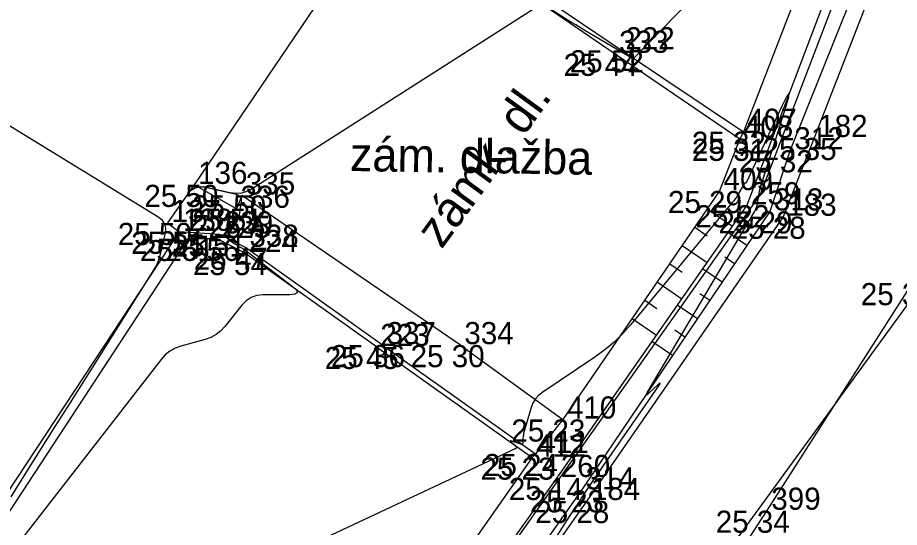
# Model space of a CAD drawing. Extents: x -702257 to -701487, y -1009871 to -1008841.
# Drawn here: x -701777.89 to -701767.92, y -1009411.95 to -1009406.19 of the extents above; entities that cross this region are included whole.
import ezdxf

# ---------------------------------------------------------------- set-up
doc = ezdxf.new("R2010")
doc.units = 0
for name, color, linetype in [('Ex_Minor Contours', 7, 'Continuous'), ('Z_body', 7, 'Continuous'), ('Z_body_cisla', 7, 'Continuous'), ('Z_body_vysky_redukovane', 7, 'Continuous'), ('Z_hrany_paty', 7, 'Continuous'), ('Z_katastr_hranice', 7, 'Continuous'), ('Z_komunikace', 7, 'Continuous'), ('Z_obruba', 7, 'Continuous'), ('Z_popisy', 7, 'Continuous'), ('Z_rozhranni', 7, 'Continuous'), ('Z_technicke_srafy', 7, 'Continuous'), ('Z_vstupy', 7, 'Continuous'), ('Z_zlabek', 7, 'Continuous')]:
    doc.layers.add(name, color=color, linetype=linetype)

# ---------------------------------------------------------------- blocks, each defined once
blk = doc.blocks.new('POINT_DISPLAY')
blk.add_line((0, 0), (0, 0))

msp = doc.modelspace()

# ---------------------------------------------------------------- linework, layer by layer
at = {"layer": 'Ex_Minor Contours'}
for points in [[(-701770.2687, -1009405.9803), (-701770.9201, -1009406.6501), (-701770.9233, -1009406.6523), (-701770.9311, -1009406.6547), (-701770.9335, -1009406.6544), (-701770.9347, -1009406.6539), (-701771.0594, -1009406.5807), (-701771.1137, -1009406.5486), (-701771.4793, -1009406.3332), (-701771.5277, -1009406.3044), (-701771.5759, -1009406.2752), (-701771.6239, -1009406.2456), (-701771.6716, -1009406.2156), (-701771.862, -1009406.0947)], [(-701772.0522, -1009406.0949), (-701775.2334, -1009408.1256), (-701775.2929, -1009408.1563), (-701775.3546, -1009408.1739), (-701775.4187, -1009408.1785), (-701775.485, -1009408.17), (-701775.762, -1009408.1084), (-701775.8227, -1009408.1027), (-701775.8768, -1009408.114), (-701775.9242, -1009408.1422), (-701775.965, -1009408.1875), (-701775.9242, -1009408.1422), (-701775.8768, -1009408.114), (-701775.8227, -1009408.1027), (-701775.762, -1009408.1084), (-701775.414, -1009408.1858), (-701775.3866, -1009408.1961), (-701775.3682, -1009408.2127), (-701775.3589, -1009408.2357), (-701775.3588, -1009408.265), (-701775.3763, -1009408.3956), (-701775.3823, -1009408.4272), (-701775.3917, -1009408.4575), (-701775.4045, -1009408.4866), (-701775.4206, -1009408.5144), (-701775.5088, -1009408.649), (-701775.5153, -1009408.6627), (-701775.5159, -1009408.6753), (-701775.5107, -1009408.6869), (-701775.4998, -1009408.6973), (-701775.4407, -1009408.7395), (-701775.4286, -1009408.7479), (-701775.4163, -1009408.7561), (-701775.4038, -1009408.7639), (-701775.3911, -1009408.7714), (-701775.3399, -1009408.801), (-701775.3272, -1009408.8085), (-701775.3148, -1009408.8165), (-701775.3027, -1009408.8249), (-701775.2909, -1009408.8337), (-701774.7769, -1009409.2294), (-701774.7342, -1009409.2696), (-701774.7252, -1009409.2984), (-701774.7498, -1009409.3159), (-701774.8082, -1009409.322), (-701775.1105, -1009409.3236), (-701775.1814, -1009409.3313), (-701775.2453, -1009409.3534), (-701775.3021, -1009409.3899), (-701775.352, -1009409.4409), (-701775.5418, -1009409.6793), (-701775.5889, -1009409.7301), (-701775.6421, -1009409.7717), (-701775.7012, -1009409.8042), (-701775.7664, -1009409.8275), (-701776.0393, -1009409.9026), (-701776.1045, -1009409.926), (-701776.1634, -1009409.9587), (-701776.2162, -1009410.0006), (-701776.2628, -1009410.0518), (-701779.331, -1009413.9893)], [(-701777.9599, -1009411.6023), (-701777.7932, -1009411.3379), (-701777.6265, -1009411.0735), (-701777.4596, -1009410.8091), (-701777.2926, -1009410.5449), (-701776.352, -1009409.0569), (-701776.3235, -1009409.0073), (-701776.2996, -1009408.9558), (-701776.2802, -1009408.9024), (-701776.2654, -1009408.8471), (-701776.2151, -1009408.6224), (-701776.2103, -1009408.5695), (-701776.2208, -1009408.5231), (-701776.2468, -1009408.4832), (-701776.2882, -1009408.4498), (-701779.1479, -1009406.6973)], [(-701772.0715, -1009412.4916), (-701771.6383, -1009411.8155), (-701771.5616, -1009411.6971), (-701771.4839, -1009411.5794), (-701771.4052, -1009411.4623), (-701771.3255, -1009411.3459), (-701770.637, -1009410.3505), (-701770.6231, -1009410.3287), (-701770.6204, -1009410.3197), (-701770.6288, -1009410.3237), (-701770.6485, -1009410.3405), (-701770.7495, -1009410.4335), (-701770.7694, -1009410.4502), (-701770.7786, -1009410.4536), (-701770.7771, -1009410.4439), (-701770.7649, -1009410.421), (-701769.5565, -1009408.387), (-701769.5437, -1009408.3631), (-701769.5333, -1009408.3383), (-701769.5253, -1009408.3126), (-701769.5197, -1009408.286), (-701769.5019, -1009408.178), (-701769.497, -1009408.1511), (-701769.4911, -1009408.1245), (-701769.4843, -1009408.098), (-701769.4765, -1009408.0718), (-701769.2023, -1009407.2017), (-701769.1685, -1009407.0855), (-701769.1638, -1009407.0442), (-701769.1884, -1009407.0778), (-701769.2421, -1009407.1862), (-701769.6504, -1009408.0577), (-701769.6525, -1009408.0601), (-701769.6557, -1009408.0608), (-701769.663, -1009408.0603), (-701769.6662, -1009408.0609), (-701769.6685, -1009408.0632), (-701769.7463, -1009408.1961), (-701769.76, -1009408.2184), (-701769.7746, -1009408.2402), (-701769.7901, -1009408.2613), (-701769.8065, -1009408.2818), (-701770.9523, -1009409.6567), (-701771.0444, -1009409.7597), (-701771.1432, -1009409.8554), (-701771.2485, -1009409.9439), (-701771.3604, -1009410.025), (-701771.9598, -1009410.4284), (-701772.0018, -1009410.462), (-701772.036, -1009410.5012), (-701772.0626, -1009410.5459), (-701772.0815, -1009410.5963), (-701772.1647, -1009410.8903), (-701772.1678, -1009410.9027), (-701772.1701, -1009410.9152), (-701772.1716, -1009410.9279), (-701772.1723, -1009410.9406), (-701772.1735, -1009410.9919), (-701772.1753, -1009411.0026), (-701772.1801, -1009411.009), (-701772.1878, -1009411.0113), (-701772.1984, -1009411.0093), (-701772.2994, -1009410.975), (-701772.3112, -1009410.9717), (-701772.3161, -1009410.9723), (-701772.314, -1009410.9768), (-701772.305, -1009410.9851), (-701772.255, -1009411.0259), (-701772.2459, -1009411.0357), (-701772.2436, -1009411.0447), (-701772.248, -1009411.0528), (-701772.2592, -1009411.0601), (-701774.4607, -1009412.0932)]]:
    msp.add_lwpolyline(points, dxfattribs=at)
at = {"layer": 'Z_hrany_paty'}
for p, q in [((-701767.68, -1009403.12), (-701769.64, -1009408.31)), ((-701769.64, -1009408.31), (-701771.79, -1009411.39)), ((-701771.79, -1009411.39), (-701776.37, -1009417.78))]:
    msp.add_line(p, q, dxfattribs=at)
at = {"layer": 'Z_katastr_hranice'}
for p, q in [((-701752.99, -1009364.98), (-701769.49, -1009408.19)), ((-701769.49, -1009408.19), (-701878.35, -1009561.73)), ((-701767.63, -1009409.16), (-701770.02, -1009412.44))]:
    msp.add_line(p, q, dxfattribs=at)
at = {"layer": 'Z_komunikace'}
for p, q in [((-701773.5, -1009404.56), (-701775.89, -1009408.08)), ((-701775.89, -1009408.08), (-701776.19, -1009408.51)), ((-701776.19, -1009408.51), (-701776.06, -1009408.61)), ((-701776.06, -1009408.61), (-701780.9, -1009415.95))]:
    msp.add_line(p, q, dxfattribs=at)
at = {"layer": 'Z_obruba'}
for p, q in [((-701767.23, -1009403.31), (-701768.88, -1009407.55)), ((-701772.99, -1009405.25), (-701771.06, -1009406.56)), ((-701771.06, -1009406.56), (-701769.68, -1009407.48)), ((-701768.88, -1009407.55), (-701769.23, -1009408.44)), ((-701769.23, -1009408.44), (-701771.45, -1009411.65)), ((-701775.96, -1009408.69), (-701780.76, -1009416)), ((-701775.63, -1009408.69), (-701775.96, -1009408.69)), ((-701775.32, -1009408.85), (-701775.63, -1009408.69)), ((-701773.83, -1009409.91), (-701775.32, -1009408.85)), ((-701773.83, -1009409.91), (-701772.07, -1009411.16)), ((-701771.45, -1009411.65), (-701776.06, -1009418.18))]:
    msp.add_line(p, q, dxfattribs=at)
at = {"layer": 'Z_rozhranni'}
for p, q in [((-701767.37, -1009403.25), (-701769.15, -1009407.69)), ((-701767.37, -1009403.25), (-701769.15, -1009407.69)), ((-701773.06, -1009405.28), (-701771.13, -1009406.6)), ((-701773.06, -1009405.28), (-701771.13, -1009406.6)), ((-701771.13, -1009406.6), (-701769.72, -1009407.56)), ((-701771.13, -1009406.6), (-701769.72, -1009407.56)), ((-701769.15, -1009407.69), (-701769.38, -1009408.38)), ((-701769.15, -1009407.69), (-701769.38, -1009408.38)), ((-701775.41, -1009408.35), (-701775.89, -1009408.08)), ((-701775.41, -1009408.35), (-701775.89, -1009408.08)), ((-701775.35, -1009408.2), (-701775.41, -1009408.35)), ((-701775.35, -1009408.2), (-701775.41, -1009408.35)), ((-701772.88, -1009409.89), (-701775.35, -1009408.2)), ((-701772.88, -1009409.89), (-701775.35, -1009408.2)), ((-701769.38, -1009408.38), (-701771.51, -1009411.53)), ((-701769.38, -1009408.38), (-701771.51, -1009411.53)), ((-701775.6, -1009408.64), (-701776.06, -1009408.61)), ((-701775.6, -1009408.64), (-701776.06, -1009408.61)), ((-701775.31, -1009408.79), (-701775.6, -1009408.64)), ((-701775.31, -1009408.79), (-701775.6, -1009408.64)), ((-701773.76, -1009409.89), (-701775.31, -1009408.79)), ((-701773.76, -1009409.89), (-701775.31, -1009408.79)), ((-701773.76, -1009409.89), (-701772.03, -1009411.12)), ((-701773.76, -1009409.89), (-701772.03, -1009411.12)), ((-701772.88, -1009409.89), (-701771.72, -1009410.73)), ((-701772.88, -1009409.89), (-701771.72, -1009410.73)), ((-701771.51, -1009411.53), (-701776.18, -1009418.09)), ((-701771.51, -1009411.53), (-701776.18, -1009418.09))]:
    msp.add_line(p, q, dxfattribs=at)
at = {"layer": 'Z_technicke_srafy'}
for p, q in [((-701770.089, -1009408.352), (-701769.805, -1009408.547)), ((-701770.23, -1009408.558), (-701770.089, -1009408.655)), ((-701769.641, -1009408.766), (-701769.856, -1009408.62)), ((-701770.372, -1009408.764), (-701770.091, -1009408.957)), ((-701770.513, -1009408.971), (-701770.374, -1009409.066)), ((-701769.781, -1009408.973), (-701769.89, -1009408.899)), ((-701769.921, -1009409.18), (-701770.143, -1009409.03)), ((-701770.654, -1009409.177), (-701770.378, -1009409.367)), ((-701770.061, -1009409.387), (-701770.173, -1009409.311)), ((-701770.796, -1009409.383), (-701770.658, -1009409.477)), ((-701770.201, -1009409.594), (-701770.429, -1009409.44)), ((-701770.937, -1009409.589), (-701770.664, -1009409.777)), ((-701770.341, -1009409.801), (-701770.457, -1009409.723)), ((-701770.481, -1009410.008), (-701770.715, -1009409.85))]:
    msp.add_line(p, q, dxfattribs=at)
at = {"layer": 'Z_vstupy'}
for p, q in [((-701769.41, -1009411.76), (-701767.77, -1009409.19)), ((-701769.41, -1009411.76), (-701767.77, -1009409.19)), ((-701770.09, -1009412.78), (-701769.41, -1009411.76)), ((-701770.09, -1009412.78), (-701769.41, -1009411.76))]:
    msp.add_line(p, q, dxfattribs=at)
at = {"layer": 'Z_zlabek'}
for p, q in [((-701767.94, -1009402.99), (-701769.68, -1009407.48)), ((-701767.94, -1009402.99), (-701769.68, -1009407.48)), ((-701769.68, -1009407.48), (-701769.72, -1009407.56)), ((-701769.68, -1009407.48), (-701769.72, -1009407.56)), ((-701769.72, -1009407.56), (-701769.95, -1009408.15)), ((-701769.72, -1009407.56), (-701769.95, -1009408.15)), ((-701769.95, -1009408.15), (-701771.72, -1009410.73)), ((-701769.95, -1009408.15), (-701771.72, -1009410.73)), ((-701771.72, -1009410.73), (-701772.03, -1009411.12)), ((-701771.72, -1009410.73), (-701772.03, -1009411.12)), ((-701772.07, -1009411.16), (-701776.57, -1009417.57)), ((-701772.07, -1009411.16), (-701776.57, -1009417.57)), ((-701772.03, -1009411.12), (-701772.07, -1009411.16)), ((-701772.03, -1009411.12), (-701772.07, -1009411.16))]:
    msp.add_line(p, q, dxfattribs=at)

# ---------------------------------------------------------------- block references
at = {"layer": 'Z_body'}
for p in [(-701771.06, -1009406.56), (-701771.13, -1009406.6), (-701769.68, -1009407.48), (-701769.72, -1009407.56), (-701768.88, -1009407.55), (-701769.15, -1009407.69), (-701775.89, -1009408.08), (-701769.95, -1009408.15), (-701775.35, -1009408.2), (-701775.41, -1009408.35), (-701769.64, -1009408.31), (-701769.38, -1009408.38), (-701769.23, -1009408.44), (-701776.19, -1009408.51), (-701776.06, -1009408.61), (-701775.6, -1009408.64), (-701775.96, -1009408.69), (-701775.63, -1009408.69), (-701775.32, -1009408.85), (-701775.31, -1009408.79), (-701773.83, -1009409.91), (-701773.76, -1009409.89), (-701772.88, -1009409.89), (-701771.72, -1009410.73), (-701772.07, -1009411.16), (-701772.03, -1009411.12), (-701771.79, -1009411.39), (-701771.51, -1009411.53), (-701771.45, -1009411.65), (-701769.41, -1009411.76)]:
    msp.add_blockref('POINT_DISPLAY', p, dxfattribs=at)

# ---------------------------------------------------------------- texts
at = {"layer": 'Z_body_cisla'}
for s, p in [('333', (-701771.085, -1009406.59)), ('222', (-701771.015, -1009406.55)), ('407', (-701769.635, -1009407.47)), ('408', (-701769.675, -1009407.55)), ('182', (-701768.835, -1009407.54)), ('312', (-701769.105, -1009407.68)), ('136', (-701775.845, -1009408.07)), ('335', (-701775.305, -1009408.19)), ('409', (-701769.905, -1009408.14)), ('259', (-701769.595, -1009408.3)), ('336', (-701775.365, -1009408.34)), ('313', (-701769.335, -1009408.37)), ('183', (-701769.185, -1009408.43)), ('137', (-701776.145, -1009408.5)), ('138', (-701776.015, -1009408.6)), ('339', (-701775.555, -1009408.63)), ('226', (-701775.915, -1009408.68)), ('225', (-701775.585, -1009408.68)), ('338', (-701775.265, -1009408.78)), ('224', (-701775.275, -1009408.84)), ('223', (-701773.785, -1009409.9)), ('337', (-701773.715, -1009409.88)), ('334', (-701772.835, -1009409.88)), ('410', (-701771.675, -1009410.72)), ('411', (-701771.985, -1009411.11)), ('412', (-701772.025, -1009411.15)), ('260', (-701771.745, -1009411.38)), ('314', (-701771.465, -1009411.52)), ('184', (-701771.405, -1009411.64)), ('399', (-701769.365, -1009411.75))]:
    msp.add_text(s, height=0.25, dxfattribs=at).set_placement(p)
at = {"layer": 'Z_body_vysky_redukovane'}
for s, p in [('25 52', (-701771.6433, -1009406.81)), ('25 44', (-701771.7133, -1009406.85)), ('25 32', (-701770.2633, -1009407.73)), ('25 31', (-701770.2617, -1009407.81)), ('25 35', (-701769.4633, -1009407.8)), ('25 32', (-701769.7333, -1009407.94)), ('25 50', (-701776.4525, -1009408.33)), ('25 29', (-701770.5333, -1009408.4)), ('25 50', (-701775.9125, -1009408.45)), ('25 51', (-701775.9517, -1009408.6)), ('25 22', (-701770.2233, -1009408.56)), ('25 29', (-701769.9633, -1009408.63)), ('25 28', (-701769.8133, -1009408.69)), ('25 50', (-701776.7525, -1009408.76)), ('25 51', (-701776.6017, -1009408.86)), ('25 51', (-701776.1417, -1009408.89)), ('25 61', (-701776.5017, -1009408.94)), ('25 56', (-701776.2133, -1009408.94)), ('25 54', (-701775.9033, -1009409.1)), ('25 47', (-701775.8933, -1009409.04)), ('25 34', (-701768.3533, -1009409.44)), ('25 45', (-701774.4133, -1009410.16)), ('25 36', (-701774.3433, -1009410.14)), ('25 30', (-701773.4425, -1009410.14)), ('25 23', (-701772.3033, -1009410.98)), ('25 23', (-701772.6533, -1009411.41)), ('25 24', (-701772.6133, -1009411.37)), ('25 14', (-701772.3317, -1009411.64)), ('25 23', (-701772.0933, -1009411.78)), ('25 28', (-701772.0333, -1009411.9)), ('25 34', (-701769.9933, -1009412.01))]:
    msp.add_text(s, height=0.25, dxfattribs=at).set_placement(p)
at = {"layer": 'Z_popisy'}
for s, height, rotation, p in [('zámk. dl.', 0.4, 54, (-701773.092, -1009408.815)), ('zám. dlažba', 0.38, 359.1, (-701774.131, -1009407.924))]:
    msp.add_text(s, height=height, rotation=rotation, dxfattribs=at).set_placement(p)

doc.saveas('drawing.dxf')
